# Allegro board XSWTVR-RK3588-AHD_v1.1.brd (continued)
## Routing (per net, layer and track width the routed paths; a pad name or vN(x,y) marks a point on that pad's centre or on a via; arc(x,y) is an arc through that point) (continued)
VCC1V2: length 191.8
  TOP w0.508: FB17.1 v2(141.55,19.26) v2(141.55,18.54) ; v2(59.98,23.92) v2(59.24,23.92) FB25.1
  BOTTOM w0.508: v2(54.41,19.67) 53.63,19.67 FB23.1 53.43,19.85 FB24.1 ; v2(54.41,19.67) 54.4,19.66 v2(54.4,18.97) v2(55.14,18.97) ; v2(54.41,19.67) v2(55.14,19.67) ; v2(59.98,23.92) v2(59.24,23.92) 59.24,20.36 58.55,19.67 v2(55.14,19.67) ; v2(55.14,19.67) 55.14,19.66 v2(55.14,18.97) ; 122.35,15.49 FB15.1 118.09,17.33 116.96,18.46 FB13.1 116.09,26.82 116.09,28.06 119.39,31.37 119.39,33.01 FB12.1 ; 122.35,15.49 139.81,15.49 141.55,17.23 v2(141.55,18.54) v2(141.55,19.26) 141.56,19.27 141.56,19.49 141.05,20 FB14.1 137.88,19.99 FB16.1 ; 122.35,15.49 117.2,10.33 76.23,10.33 70.22,16.35 57.72,16.35 55.14,18.94 ; 55.14,18.94 55.14,16.58 54.26,15.7 39.39,15.7 FB21.1 37.11,17.19 32.51,21.79 FB22.1 31.92,25.81 31.33,26.41 31.33,28.08 32.06,28.81 34.35,28.81 35.16,29.63 35.16,33.09 36.64,34.57 36.64,34.67 37.32,35.34 FB26.1 ; 55.14,18.94 v2(55.14,18.97)
VCC3V3_PHY0: length 33.5
  TOP w0.254: v1(127.27,85.37) 127.22,85.41 U17.29 ; R160.1 v1(133.94,82.99) ; U17.11 v1(122.77,90.21) ; R158.1 v1(133.64,81.03) ; U17.40 v1(128.85,90.21)
  TOP w0.381: R175.1 v1(119.2,91.43) C269.1 R172.2
  L3 w0.381: v1(122.77,90.21) v1(128.85,90.21)
  BOTTOM w0.381: 129.11,85.56 129.11,88.67 128.74,89.04 C273.1 128.74,90.09 v1(128.85,90.21) ; 129.11,85.56 129.11,85.44 133.51,81.03 133.64,81.03 ; 129.11,85.56 128.7,85.96 C272.1 127.86,85.96 v1(127.27,85.37) ; 122.59,90.53 122.59,90.51 122.77,90.34 v1(122.77,90.21) 122.77,89.74 C271.1 ; 122.59,90.53 C270.1 ; 122.59,90.53 122.58,90.52 120.11,90.52 v1(119.2,91.43) ; 133.64,81.03 v1(133.64,81.03) ; 133.64,81.03 133.94,81.33 v1(133.94,82.99)
VCC3V3_PHY1: length 55.7
  TOP w0.203: U19.11 145.08,90.28 v1(144.67,90.68)
  TOP w0.254: R219.1 v1(141.36,91.49) ; U19.29 149.26,85.51 v1(149.32,85.44) ; U19.40 150.92,90.28 151.31,90.66 v1(151.31,90.66)
  TOP w0.381: R203.1 v1(156.12,84.79) ; R206.2 v1(152.98,79.84) ; R201.1 v1(155.73,81.1)
  BOTTOM w0.381: 148.11,81.24 140.69,81.24 140.14,81.79 140.14,84.31 140.53,84.7 R216.2 140.76,84.81 140.76,90.9 v1(141.36,91.49) 142.39,91.49 143.84,90.04 C294.1 144.41,90.41 v1(144.67,90.68) ; 148.11,81.24 149.5,79.84 v1(152.98,79.84) 154.83,79.84 155.73,80.74 v1(155.73,81.1) 155.73,84.39 v1(156.12,84.79) ; 148.11,81.24 149.97,83.1 149.97,85.44 ; 151.31,90.42 151.31,88.4 151.58,88.12 151.58,86.94 151.2,86.56 C298.1 C296.1 149.97,85.44 ; 151.31,90.42 150.93,90.04 C299.1 ; 151.31,90.42 v1(151.31,90.66) 150.97,91 C295.1 ; 149.97,85.44 149.32,85.44 v1(149.32,85.44)
VCC3V3_SD: length 27.8
  TOP w0.305: U22.7 24.59,29.59 23.86,30.32 23.86,32.03
  TOP w0.381: 10.24,32.62 10.31,32.69
  TOP w0.508: 23.86,32.03 22.44,33.45 C323.1 10.31,32.69 ; 10.24,32.62 C324.1 10.06,26.58 11.55,25.09 J22.4
VCC3V3_SYS: length 504.7
  TOP w0.254: D21.1 v1(23.61,90.79) ; v1(23.64,92.36) R112.1 21.45,92.36 Q7.1 ; 25.75,30.33 25.47,30.33 25.25,30.1 U22.6 ; 25.75,30.33 25.75,30.64 25.61,30.77 C321.1 25.6,31.31 C322.1 24.81,30.31 v1(24.76,30.27) ; 25.75,30.33 U22.5 ; U28.9 34.7,77.2 v1(34.71,77.21) 34.73,77.21 35.2,76.74 C365.1 35.28,76.76 ; v1(59.5,146.02) 60.21,146.02 R323.2 R324.2 ; R114.1 R115.1 v1(26.43,94.84) ; R36.1 111.95,28.93 v1(111.75,28.72) ; R117.1 v1(23.6,89.47) ; R302.2 v1(60.26,130.88)
  TOP w0.305: FB18.1 33.44,31.41 32.67,30.64 v1(30.08,30.64)
  TOP w0.381: R172.1 v1(116.46,89.86) v1(115.96,89.86)
  TOP w0.508: v2(57.76,32.87) v2(57.1,32.87) ; FB9.1 112.95,36.82 112.95,36.82 v2(112.09,36.82) 112.09,37.51 112.08,37.52 112.08,38.29 D19.1 ; v1(90.88,19.96) 90.86,19.98 90.86,20.7 v1(90.87,20.71) 89.97,20.71 C349.1 89.85,20.71 88.77,20.71 C350.2 88.69,20.72 U25.16 ; v2(34.44,32.22) 34.32,32.34 34.26,32.34 34.26,32.34 FB18.1 ; v2(64.97,34.84) C375.2 65.75,34.84 U29.5 ; v2(96.33,130.29) 96.31,130.28 C257.2 ; v2(142.22,30.88) v2(141.55,30.88) ; R130.1 v2(72.71,124.69) ; U26.5 C371.2 v2(89,37.38) ; C347.1 v1(78.89,18.39)
  TOP w0.559: F2.1 96.3,128.96 C257.2
  TOP w0.762: v1(110.79,18.31) v1(111.33,18.85)
  L3 w0.254: v1(30.08,30.64) 25.13,30.64 v1(24.76,30.27)
  L3 w0.762: v2(34.44,32.22) 37.13,34.91 50.98,34.91 53.54,32.35 56.58,32.35 v2(57.1,32.87) v2(57.76,32.87) 63,32.87 v2(64.97,34.84) 66.29,34.84 68.89,32.24 v2(74.76,32.24) 74.76,32.24 74.76,33.42 ; 74.76,33.42 79.74,33.42 ; 74.76,33.42 74.76,36.14 v2(74.82,36.2) ; v2(151.54,127.28) 151.54,118.8 146.02,113.28 140.55,113.28 138.3,111.03 138.3,83.87 ; 85.42,33.42 85.35,33.49 85.35,33.5 v1(85.35,35.61) 85.35,35.64 87.1,37.38 v2(89,37.38) 91.37,35.02 99.12,35.02 100.93,36.82 v2(112.09,36.82) 112.09,36.01 111.75,35.67 v1(111.75,28.72) ; 85.42,33.42 86.37,32.48 v1(87.49,32.48) ; 85.42,33.42 79.74,33.42 ; v2(79.73,30.08) 79.73,33.41 79.74,33.42
  L3 w1.016: 138.3,83.87 139.18,82.98 140.31,82.98 v2(141.02,82.27) ; v2(141.02,82.27) v2(141.87,82.27) 141.87,82.49 143.37,83.99 152.74,83.99 ; v2(141.02,82.27) 141.02,80.74 v2(139.79,79.5) ; 68.41,32.71 v2(68.41,30.71)
  POW04 w0.305: v1(34.71,77.21) 33.36,77.21 31.94,78.63 18.06,78.63 14.7,75.28
  POW04 w0.508: 63.81,127.89 63.76,127.89 63.15,127.28 ; 63.81,127.89 63.9,127.89 64.51,127.28 ; 63.81,127.89 63.81,144.62 62.42,146.02 v1(59.5,146.02) ; 63.81,127.89 63.81,127.3 63.83,127.28 ; v1(115.96,89.86) v1(116.46,89.86) 116.9,89.86 120.34,86.42 130.44,86.42 132.34,84.51 132.85,84.51 132.86,84.51 138.78,84.51 v2(141.02,82.27) ; v2(96.33,130.29) 91.7,134.92 91.7,152.31 92.08,152.69 D43.3
  POW04 w0.762: 97.15,127.28 97.15,129.47 v2(96.33,130.29) ; 97.15,127.28 97.25,127.18 150.63,127.18 150.72,127.28 v2(151.54,127.28) ; 97.15,127.28 73.41,127.28 ; v1(60.26,130.88) 60.26,128.92 61.89,127.28 72.01,127.28 ; 73.41,127.28 72.67,127.28 ; 73.41,127.28 72.71,126.58 ; 72.67,127.28 72.01,127.28 ; 72.67,127.28 72.71,127.24 72.71,126.58 ; 72.01,127.28 72.71,126.58 72.71,126.58 ; 72.71,126.58 v2(72.71,124.69)
  BOTTOM w0.381: R274.1 85.77,36.03 v1(85.35,35.61)
  BOTTOM w0.508: R291.1 v2(81.89,25.55) R287.2 ; v1(26.43,94.84) 26.12,94.84 v1(23.64,92.36) 23.61,92.33 ; v2(79.73,30.08) 79.8,30.16 R289.2 79.81,30.85 R293.1 ; R275.1 v2(74.82,36.2) R271.2 ; R286.2 68.89,25.37 v2(68.9,25.38) R290.1 ; 23.61,92.33 v1(23.61,90.79) 23.6,90.78 v1(23.6,89.47) ; 23.61,92.33 21.95,92.33 15.57,98.7 9.34,98.7 7.57,100.47 v2(7.57,103.53) ; v2(142.22,30.88) 141.85,31.25 FB11.1 ; R288.2 v2(68.41,30.71) R292.1 ; R274.1 R270.2 ; R276.1 R272.2 86.76,31.74 v1(87.49,32.48) ; v2(141.02,82.27) v2(141.87,82.27) R211.1 140.87,83.69 R216.1 ; R277.1 74.68,32.24 v2(74.76,32.24) 75.48,31.52 R273.2
  BOTTOM w0.762: v2(57.1,32.87) 57.26,33.03 57.26,36.99 56.06,38.19 49.48,38.19 48.71,38.95 48.71,41.7 49.52,42.51 54.39,42.51 55.16,43.28 C107.1
  vias: v2(2.92,65.94) v2(2.91,65.24) v2(2.91,64.49) v2(2.9,63.79) v2(3.59,65.94) v2(3.58,65.24) v2(3.58,64.49) v2(3.57,63.79) v2(4.1,104.23) v2(4.09,103.53) v2(4.28,65.94) v2(4.27,65.24) v2(4.27,64.49) v2(4.26,63.79) v2(4.77,104.23) v2(4.76,103.53) v2(4.94,63.78) v2(4.97,65.93) v2(4.95,65.23) v2(4.96,64.48) v2(5.46,104.23) v2(5.45,103.53) v2(5.64,63.78) v2(5.67,65.93) v2(5.65,65.23) v2(5.66,64.48) v2(6.12,103.52) v2(6.15,104.22) v2(6.82,103.52) v2(6.85,104.22) v2(7.56,104.21) v2(54.66,21.69) v2(54.66,21.02) v2(65.98,15.4) v2(65.98,14.51) v2(65.97,13.7) v2(66.92,15.39) v2(66.92,14.5) v2(66.91,13.69) v2(139.11,21.83) v2(139.11,21.16) v2(142.89,37.73) v2(143.8,37.75) v2(144.67,37.77) v2(152.86,66.26) v2(152.87,65.36) v2(153.74,66.28) v2(153.75,65.38)
VCC3V9_5G: length 158.1
  L3 w0.762: v2(117.65,69.48) 118.68,70.51 128.48,70.51 136.82,78.84 136.82,111.51 139.82,114.52 145.59,114.52 150.49,119.41 v2(150.49,128.66)
  POW04 w0.508: v2(150.49,128.66) 145.93,133.22 96.4,133.22 93.22,136.4 D43.1
  BOTTOM w0.254: 12.85,41.65 12.43,41.23 R63.1 11.14,41.23 C106.1
  vias: v2(10,46.99) v2(10,46.32) v2(10.01,45.61) v2(10.72,46.99) v2(10.72,46.32) v2(10.73,45.61) v2(11.42,46.99) v2(11.42,46.32) v2(11.43,45.61) v2(12.14,46.99) v2(12.14,46.32) v2(12.15,45.61) v2(113.99,62.46) v2(113.99,61.74) v2(113.99,61.04) v2(113.99,60.32) v2(114.71,63.19) v2(114.71,62.47) v2(114.71,61.75) v2(114.71,61.05) v2(114.71,60.33) v2(115.37,62.47) v2(115.37,61.75) v2(115.37,61.05)
VCC5V0_SYS: length 84
  TOP w0.254: v1(20.43,87.42) D20.1 20.42,88.16 Q9.1
  TOP w0.305: U20.5 37.79,60.77 37.82,60.74 C308.1
  TOP w0.508: v2(78.24,27.47) C367.1 79.06,27.48 U10.10 ; U29.10 C374.1 75.41,34.84 75.97,35.4 v2(75.97,35.4) ; v2(89.31,24.92) C369.1 88.46,24.94 U10.3 ; v2(66.31,36.65) 65.74,37.22 C373.1 U29.3 ; v1(15.69,96.36) v1(15.69,96.96) D22.1 ; v2(88.98,34.72) 88.86,34.84 C370.1 U26.3 ; U26.10 79.19,37.38 C372.1 79.18,37.36 v2(79.18,36.37) ; C75.1 75.48,24.81 ; 75.48,24.81 74.83,25.46 74.83,25.5 v2(74.83,25.5) ; 75.48,24.81 U9.3 ; v2(97.71,17.14) v2(97.71,16.39) 97.71,14.92 98.48,14.15 R30.1 100.81,14.15 C56.2 101.36,14.57 U6.1 ; v2(65.24,28.18) C366.1 66.07,27.35 U9.10
  BOTTOM w0.762: v2(37.35,59.68) v2(36.6,59.68) 35.87,59.68 v2(35.85,59.69) 31.33,59.69 27.61,63.41 27.61,80.16 20.43,87.34 v1(20.43,87.42) 16.98,90.87 16.98,95.07 v1(15.69,96.36) v1(15.69,96.96)
  vias: v2(99.25,29.37) v2(123.23,47.07) v2(123.23,46.34) v2(123.23,45.65) v2(123.94,47.08) v2(123.94,46.35) v2(123.94,45.66) v2(124.61,47.08) v2(124.61,46.35) v2(124.61,45.66)
VCC5V0_USB30_HOST0: length 27.5
  TOP w0.254: R232.2 34.71,64.14 35.28,64.71 R236.1
  TOP w0.762: 25.22,63.3 C312.1
  TOP w1.016: R232.2 34.71,61.07 U20.1 31.57,60.77 30.19,62.15 C310.1 27.11,63.3 27.11,63.3 C311.1 ; C311.1 26.03,60.89 23.71,58.57 J20.1 ; C311.1 25.22,63.3
VCC5V_HDMI_TX0: length 15.8
  TOP w0.305: J17.18 7.78,90.75
  TOP w0.508: C244.1 12.91,98.24 D22.2 7.07,96.96 6.21,96.1 6.21,91.99 7.45,90.75 7.78,90.75
VCC_1V8: length 159.4
  TOP w0.254: v1(25.91,97.12) 26.69,97.12 R119.2 ; R120.2 v1(22.75,96.71)
  TOP w0.381: v1(67.98,125.15) 68.55,125.15 71.64,128.25 R133.1
  TOP w0.508: v2(54.86,120.66) 54.86,119.73 v2(54.84,119.71) FB27.1 ; R347.1 8.94,102.53
  TOP w0.635: v2(52.56,127.88) v2(52.56,126.92) ED41.1
  POW04 w0.508: v1(67.98,125.15) 66.83,124 54.86,124 54.85,124.01
  POW04 w0.762: v1(117.67,84.45) v1(117.67,84.94)
  POW04 w1.016: v1(117.67,84.94) 114.75,84.94 108.59,91.1 108.59,104.95 105.81,107.73 34.23,107.73 33.65,108.31 18.37,108.31 18.05,107.98
  BOTTOM w0.381: R167.1 v1(117.67,84.45) v1(117.67,84.94)
  BOTTOM w0.508: v2(12.97,100.63) 12.97,100.49 13.68,99.78 17.22,99.78 20.28,96.71 v1(22.75,96.71) 22.75,96.76 23.11,97.12 v1(25.91,97.12)
  vias: v2(10.92,102.76) v2(10.91,102.06) v2(10.91,101.37) v2(10.91,100.62) v2(11.63,102.75) v2(11.62,102.05) v2(11.62,101.36) v2(11.6,100.61) v2(12.34,102.03) v2(12.29,100.62) v2(12.35,102.72) v2(12.35,101.33) v2(12.98,102.74) v2(12.97,102.04) v2(12.98,101.35)
VCC_DCIN: length 3.4
  TOP w0.508: R13.2 38.62,110.71 ; R22.2 148.39,61.39
  vias: v2(8.46,14.88) v2(8.46,13.88) v2(8.46,12.88) v2(9.46,14.88) v2(9.46,13.88) v2(9.46,12.88) v2(10.46,14.88) v2(10.46,13.88) v2(10.46,12.88) v2(20.4,7.67) v2(20.4,6.67) v2(20.4,5.67) v2(21.4,7.67) v2(21.4,6.67) v2(21.4,5.67) v2(22.4,7.67) v2(22.4,6.67) v2(22.4,5.67) v2(34.33,116.34) v2(34.34,115.45) v2(34.34,114.49) v2(35.34,115.45) v2(35.34,114.49) v2(35.35,116.34) v2(36.3,116.34) v2(36.3,115.45) v2(36.31,114.54) v2(37.3,116.34) v2(37.32,115.45) v2(37.34,114.55) v2(38.27,116.35) v2(38.29,115.45) v2(38.27,114.54) v2(39.63,7.67) v2(39.63,6.67) v2(39.63,5.67) v2(40.63,7.67) v2(40.63,6.67) v2(40.63,5.67) v2(41.63,7.67) v2(41.63,6.67) v2(41.63,5.67) v2(58.88,7.59) v2(58.88,6.59) v2(58.88,5.59) v2(59.88,7.59) v2(59.88,6.59) v2(59.88,5.59) v2(60.88,7.59) v2(60.88,6.59) v2(60.88,5.59) v2(78.11,7.6) v2(78.11,6.6) v2(78.11,5.6) v2(79.11,7.6) v2(79.11,6.6) v2(79.11,5.6) v2(80.11,7.6) v2(80.11,6.6) v2(80.11,5.6) v2(97.36,7.58) v2(97.36,6.58) v2(97.36,5.58) v2(98.36,7.58) v2(98.36,6.58) v2(98.36,5.58) v2(99.36,7.58) v2(99.36,6.58) v2(99.36,5.58) v2(116.63,7.59) v2(116.63,6.59) v2(116.63,5.59) v2(117.63,7.59) v2(117.63,6.59) v2(117.63,5.59) v2(118.63,7.59) v2(118.63,6.59) v2(118.63,5.59) v2(135.86,7.61) v2(135.86,6.61) v2(135.86,5.61) v2(136.86,7.61) v2(136.86,6.61) v2(136.86,5.61) v2(137.86,7.61) v2(137.86,6.61) v2(137.86,5.61) v2(156.25,72.37) v2(156.26,71.43) v2(156.25,70.51) v2(156.27,69.61) v2(156.43,61.57) v2(156.42,60.67) v2(156.42,59.75) v2(156.44,58.85) v2(157.2,72.36) v2(157.21,71.41) v2(157.23,70.52) v2(157.25,69.62) v2(157.39,61.56) v2(157.38,60.66) v2(157.4,59.77) v2(157.41,58.86) v2(158.14,70.53) v2(158.16,72.36) v2(158.16,71.41) v2(158.16,69.63) v2(158.34,61.56) v2(158.33,60.66) v2(158.31,59.77) v2(158.33,58.87)
VCCA1V8_CODEC: length 33
  TOP w0.203: v1(47.13,113.89) 47.27,113.89 47.7,114.32 U23.16
  TOP w0.254: R257.2 v1(55.26,111.97) ; R267.2 v1(53.84,115.89)
  TOP w0.508: v2(49.27,119.23) 49.39,119.35 49.39,121.3 49.92,121.83 C342.1 51.99,120.88 C341.1 51.99,119.8 FB27.2 ; FB28.1 46.16,111.41 v1(46.16,111.83) 46.16,112.36 v1(46.18,112.37)
  BOTTOM w0.254: C332.1 51.24,118.49 v1(53.84,115.89) 55.26,114.47 v1(55.26,111.97)
  BOTTOM w0.508: v2(49.27,119.23) 49.27,118.79 C337.1 ; v1(46.16,111.83) 46.16,112.36 v1(46.18,112.37) 46.26,112.45 46.26,113.02 v1(47.13,113.89) ; C333.1 47.75,114.16 47.71,114.2 47.43,114.2 v1(47.13,113.89) ; v1(47.13,113.89) 47.13,114.15 47.14,114.16 47.14,114.6 47.11,114.64 47.11,115.5 47.13,115.53 47.13,117.99 47.64,118.5 C336.1 C337.1 ; C337.1 C331.1 50.89,118.5 C332.1
VCCIO_PHY0: length 26.9
  TOP w0.254: R169.1 v1(124.13,82.3) ; R164.1 v1(120.97,82.3) ; R174.1 v1(122.02,82.3) ; R176.1 v1(119.24,89.38) ; R171.1 v1(123.08,82.3) ; v1(126.82,85.07) U17.28
  BOTTOM w0.381: 126.78,86.65 C267.1 125.81,83.54 124.57,82.3 v1(124.13,82.3) v1(123.08,82.3) v1(122.02,82.3) v1(120.97,82.3) 120.97,82.73 ; 126.78,86.65 C268.1 ; 126.78,86.65 126.73,86.59 126.73,85.17 v1(126.82,85.07) ; R167.2 117.88,82.74 C266.1 120.96,82.74 120.97,82.73 ; v1(119.24,89.38) 120.26,89.38 120.97,88.67 120.97,82.73
VCCIO_PHY1: length 23.3
  TOP w0.254: R208.1 v1(143.09,82.36) ; R215.1 v1(145.19,82.36) ; R218.1 v1(144.14,82.36) ; U19.28 148.86,85.22 v1(148.83,85.19) ; R213.1 v1(146.25,82.36)
  TOP w0.381: R220.1 v1(141.36,89.36)
  BOTTOM w0.381: v1(148.83,85.19) 148.83,85.22 148.81,85.23 148.81,86.34 C293.1 C291.1 C292.1 147.15,83.26 v1(146.25,82.36) v1(145.19,82.36) v1(144.14,82.36) v1(143.09,82.36) 143.09,84.04 142.43,84.69 R211.2 141.87,88.85 v1(141.36,89.36)
VCCIO_WL: length 16.6
  TOP w0.127: v1(77.8,140.51) 78.14,140.16 R129.1
  TOP w0.203: v1(72.4,132.18) 72.69,131.88 U14.34
  TOP w0.508: R133.2 C255.1 U14.34
  L3 w0.203: v1(72.4,132.18) 72.4,136.87 76.03,140.51 v1(77.8,140.51)
VDD10_PHY0: length 38.3
  TOP w0.254: U17.3 126.82,91.39 v1(126.83,91.39) ; U17.38 129.34,89.41 v1(129.34,89.41) ; v1(124.82,91.38) 124.82,91.38 U17.8 ; U17.21 124.02,85.86 123.77,85.61 v1(123.55,85.61)
  BOTTOM w0.381: 129.46,89.41 129.72,89.16 129.72,86.4 131.58,84.54 134.19,84.54 134.73,83.99 134.73,80.06 134.24,79.57 v1(129.84,79.57) 129.84,80.1 v1(129.85,80.11) 129.85,80.6 v1(129.87,80.62) ; 129.46,89.41 129.46,90.61 128.69,91.39 v1(126.83,91.39) 126.49,91.05 C280.1 C279.1 125.16,91.05 ; 129.46,89.41 v1(129.34,89.41) ; 125.16,91.05 124.84,91.05 124.46,90.67 124.46,89.3 124.08,88.92 122.65,88.92 122.16,88.43 122.16,87.02 122.54,86.64 C281.1 C277.1 124.03,86.1 v1(123.55,85.61) ; 125.16,91.05 v1(124.82,91.38)
VDD10_PHY1: length 33.9
  TOP w0.203: U19.21 146.06,85.85 145.85,85.64 145.78,85.64 v1(145.65,85.64) ; v1(146.72,91.73) 146.72,91.72 146.86,91.58 U19.8 ; v1(148.83,91.68) 148.86,91.66 U19.3
  TOP w0.254: U19.38 151.37,89.48 152.2,90.3 v1(152.2,90.46)
  BOTTOM w0.381: C305.1 C302.1 C303.1 ; C305.1 v1(148.83,91.68) ; C305.1 149.39,91.62 151.69,91.62 152.2,91.12 v1(152.2,90.46) C306.1 152.54,89.7 152.93,89.32 152.93,82.07 151.71,80.85 v1(150.59,80.85) v1(150.14,80.85) v1(149.71,80.85) v1(149.3,80.85) ; C303.1 146.72,91.31 v1(146.72,91.73) ; C303.1 146.55,91.07 146.17,90.69 146.17,89.86 144.54,88.23 144.54,86.94 144.92,86.56 C307.1 C301.1 146.19,86.18 v1(145.65,85.64)
VINN1: length 0.9
  TOP w0.203: R73.1 93.04,9.84 C120.1
VINN2: length 0.9
  TOP w0.203: C121.1 117.34,9.74 R76.1
VINN3: length 0.8
  TOP w0.203: C123.1 134.03,11.44 R81.1
VINN4: length 0.8
  TOP w0.203: R82.1 144.03,10.65 C112.1
VINN5: length 0.9
  TOP w0.203: C176.1 18.39,10.62 R90.1
VINN6: length 0.9
  TOP w0.203: R93.1 37.54,9.54 C178.1
VINN7: length 1.3
  TOP w0.203: C179.1 50.49,11.55 50.85,11.19 R99.1
VINN8: length 0.8
  TOP w0.203: R97.1 69.94,11.38 C187.1
VINP1: length 1.9
  TOP w0.203: C119.1 92.17,11.43 R78.2 92.16,10.44 R71.2
VINP1_COAX: length 6.2
  TOP w0.203: R71.1 91.27,10.31 D11.1 91.27,9.34 91.27,9.33 J9.5
VINP2: length 1.9
  TOP w0.203: R74.2 R77.2 116.49,11.29 C111.1
VINP2_COAX: length 10
  TOP w0.203: R74.1 115.55,10.24 D12.1 112.43,9.26 110.51,7.34 J10.5
VINP3: length 1.9
  TOP w0.203: C122.1 133.19,12.2 R79.2 133.19,11.34 R72.2
VINP3_COAX: length 7.8
  TOP w0.203: J11.5 129.76,7.92 131.1,9.27 D14.1 132.19,9.35 R72.1
VINP4: length 1.9
  TOP w0.203: R75.2 144.9,9.84 R80.2 144.85,9.81 C124.1
VINP4_COAX: length 9.1
  TOP w0.203: R75.1 145.91,10.85 D13.1 147.94,10.85 149,9.79 J12.5
VINP5: length 2.2
  TOP w0.203: C175.1 16.59,11.86 R94.2 R88.2
VINP5_COAX: length 6.8
  TOP w0.203: R88.1 15.7,10.31 D15.1 14.3,7.95 J13.5
VINP6: length 2.2
  TOP w0.203: 35.66,10.33 R95.2 36.16,10.88 C177.1
  TOP w0.254: R91.2 R95.2
VINP6_COAX: length 6.3
  TOP w0.203: J14.5 33.54,9.44 D16.1
  TOP w0.254: R91.1 34.48,9.46 D16.1
VINP7: length 2.2
  TOP w0.203: 49.87,10.36 R98.2 ; R98.2 50.11,10.55 50.11,11.17 C186.1 ; R98.2 49.93,10.34 R89.2
VINP7_COAX: length 6.6
  TOP w0.203: J15.5 52.78,8.63 D17.1 51.03,9.45 R89.1
VINP8: length 2.4
  TOP w0.203: C180.1 69.1,9.65 69.6,10.15 69.6,10.16 69.94,10.51 R96.2 ; 69.89,10.61 R96.2 ; R96.2 69.94,10.61 R92.2
VINP8_COAX: length 6.5
  TOP w0.203: R92.1 71.03,9.69 D18.1 72.03,9.66 J16.5
5G_3V3: length 30.5
  TOP w0.254: v1(46.57,45.74) v1(46.57,44.72) 46.57,44.72 v1(46.57,43.7)
  L3 w0.508: v1(29.68,36.17) 29.68,37.98 31.41,39.71 40.18,39.71 44.17,43.7 v1(46.57,43.7)
  BOTTOM w0.254: Q3.3 48.45,46.18 47.13,46.18 46.69,45.74 v1(46.57,45.74) R54.2 ; R345.1 v1(29.68,36.17) ; R53.2 v1(46.57,44.72) ; R52.2 v1(46.57,43.7)
5G_3V9: length 20
  BOTTOM w0.508: v2(18.59,40.76) 18.59,41.45 18.15,41.89 C83.2 C82.2 18.15,46.22 C80.2 18.13,47.04 C81.2 18.15,48.06 C79.1 19.23,48.71 20.45,47.48 22.61,47.48 J2.2 ; 41.37,46.9 42.21,47.74 C87.1 C91.1 C92.1 C88.1 ; v2(17.21,40.75) 16.29,40.75 Q2.3
  vias: v2(17.21,40.03) v2(17.88,40.75) v2(17.88,40.03) v2(18.59,40.04) v2(49.39,50.05) v2(49.39,49.39) v2(49.4,48.67) v2(50.11,50.05) v2(50.11,49.39) v2(50.12,48.67) v2(50.81,50.05) v2(50.81,49.39) v2(50.82,48.67) v2(51.54,50.05) v2(51.54,49.39) v2(51.55,48.67)
5G_PWR_OFF: length 113.2
  TOP w0.127: v1(106.88,33.81) 106.88,35.91 106.89,35.91 J24.3
  L3 w0.127: v1(23.6,45.77) 23.6,44.81 19.32,40.54 19.32,32.12 22.64,28.8 50.35,28.8 51.88,27.28 60.6,27.28 60.99,26.89 72.8,26.89 73.34,26.35 84.61,26.35 87.89,29.63 96.96,29.63 99.77,32.43 105.51,32.43 v1(106.88,33.81)
  BOTTOM w0.127: v1(23.6,45.77) 23.8,45.98 J2.6
5G_PWRER_CTR: length 95.7
  TOP w0.127: J24.8 v1(104.39,33.84)
  L3 w0.127: v1(19.72,36.31) 20.14,35.9 20.14,31.78 22.86,29.06 50.48,29.06 51.74,27.8 56.68,27.8 56.91,28.03 57.21,28.03 57.57,27.67 72.45,27.67 73.52,26.6 84.51,26.6 87.78,29.88 87.82,29.88 87.92,29.98 96.87,29.98 99.65,32.75 103.3,32.75 v1(104.39,33.84)
  BOTTOM w0.127: R67.1 v1(19.72,36.31)
5G_RESET: length 84.4
  TOP w0.127: J24.12 v1(102.39,33.52)
  L3 w0.127: v1(23.75,29.78) 36.2,29.78 36.67,29.31 50.71,29.31 51.55,28.47 53.26,28.47 53.94,29.15 72.35,29.15 73.61,27.89 85.34,27.89 87.71,30.26 96.71,30.26 99.71,33.26 102.13,33.26 v1(102.39,33.52)
  BOTTOM w0.127: R55.1 23.75,30.15 23.75,30.15 v1(23.75,29.78)
5G_USB_DM: length 43
  TOP w0.127: U28.5 v1(31.8,76.8)
  L3 w0.127: v1(31.8,76.8) 31.5,77.06 28.81,77.06 24.51,72.76 24.51,42.39 v1(24.67,42.23)
  BOTTOM w0.127: v1(24.67,42.23) 24.44,42.01 24.44,40.53 24.55,40.42 J2.9
5G_USB_DP: length 43.5
  TOP w0.127: U28.3 v1(31.75,77.6)
  L3 w0.127: v1(31.75,77.6) 31.53,77.34 28.69,77.34 24.23,72.88 24.23,42.53 v1(23.94,42.23)
  BOTTOM w0.127: J2.7 24.05,40.39 24.16,40.5 24.16,42.01 v1(23.94,42.23)
5G_VBUS: length 23.1
  TOP w0.305: v1(32.38,79.81) 35.94,79.81 36.38,79.36 R330.1 ; v1(32.4,74.62) 29.97,72.2 J21.1
  BOTTOM w0.305: v1(32.4,74.62) 32.4,75.08 32.38,75.1 v1(32.38,79.81)
5G_W_DISABLE1#: length 24.5
  BOTTOM w0.127: J2.8 24.3,44.72 25.76,43.27 25.76,38.93 24.97,38.14 23.07,38.14 22.47,37.54 22.47,29.95 23.13,29.28 25.62,29.28 25.74,29.4 R51.1
5G_WAKE_MCU: length 78.5
  TOP w0.127: v1(96.02,30.98) 96.02,30.4 97.17,29.25 97.17,27.85 97.48,27.53 U8.33
  L3 w0.127: v1(96.02,30.98) 87.44,30.98 84.86,28.4 74.05,28.4 72.78,29.66 66.82,29.66 66.67,29.82 37.33,29.82 36.54,30.61 32.09,30.61 29.97,32.72 29.94,32.72 v1(29.68,32.98)
  BOTTOM w0.127: v1(29.68,32.98) R345.2 28.83,33.47 Q32.3
5G_WAKE_ON_WAN: length 3.9
  BOTTOM w0.127: J2.23 28.05,38.8 28.37,38.48 Q32.2
5G_WAKEUP_IN: length 118.1
  TOP w0.127: U1.214 88.31,106.87 v1(88.77,106.42)
  L3 w0.127: v1(31.8,49.09) 32.06,49.35 36.74,49.35 39.31,51.92 39.31,53.67 42.21,56.58 42.21,100.22 49.33,107.34 87.89,107.34 88.27,107.71 90.72,107.71 91.7,106.73 91.7,106.38 91.41,106.09 90.12,106.09 89.79,106.42 v1(88.77,106.42)
  BOTTOM w0.127: J2.38 v1(31.8,49.09)
5G_WWAN_LED#: length 158.5
  TOP w0.203: v1(88.98,149.46) 88.24,149.46 86.77,147.99 R348.1
  L3 w0.127: v1(88.98,149.46) 88.98,146.94 85.92,143.88 85.92,112.71 81.55,108.34 67.58,108.34 66.12,109.81 61.44,109.81 60.38,108.75 56.92,108.75 55.21,110.46 50.37,110.46 40.23,100.31 40.23,57.47 34.16,51.41 32.3,51.41 30.62,49.73 25.52,49.73 v1(25.12,49.34)
  BOTTOM w0.127: J2.10 24.8,49.02 v1(25.12,49.34)
27M_CLK_XI: length 5.6
  TOP w0.203: R83.2 120.31,36.58 ; 120.31,36.58 R85.1 ; 120.31,36.58 120.21,36.67 C132.1 119.05,36.41 117.21,36.41 Y1.3
27M_CLK_XI1: length 5.6
  TOP w0.203: R105.1 35.86,36.44 ; 35.86,36.44 35.76,36.53 C197.1 34.61,36.27 32.77,36.27 Y2.3 ; 35.86,36.44 R101.2
ACC: length 25.9
  TOP w0.381: R304.2 54.92,139.84 51.53,143.23 42.27,143.23 U24.C4
ACC_CHECK: length 159.7
  TOP w0.102: 59.11,129.33 59.54,129.76 59.77,129.76 60.21,129.32 R302.1
  TOP w0.127: ED45.2 60.27,129.34 R302.1 ; R39.2 104.18,31.4 103.58,32 99.69,32 97.89,33.81 J24.21 97.89,37.91 99.5,39.53 v1(99.87,39.53) ; Q30.3 59.11,129.33 59.11,127.65 58.54,127.08 58.54,111.65 56.07,109.18 v1(54.63,109.18)
  BOTTOM w0.127: v1(54.63,109.18) 52.06,106.61 51.67,106.61 51.67,106.61 49.99,106.61 49.18,105.8 49.18,61.22 49.48,60.92 56.69,60.92 58.46,59.15 71.48,59.15 73.15,57.48 73.15,42.57 73.62,42.1 76.35,42.1 76.6,41.85 97.55,41.85 v1(99.87,39.53)
AHD_I2C_SCL: length 163.4
  TOP w0.127: v1(130.67,38.03) 130.85,37.86 138.13,37.86 139.62,36.37 139.62,28.38 138.8,27.56 U11.49 ; v1(61.94,24.58) 61.88,24.64 61.88,26.58 60.31,28.15 55.98,28.15 R107.2 55.26,27.42 U13.49 ; v1(83.13,40.27) 82.18,41.23 80.97,41.23 80.31,41.89 U1.99
  L3 w0.127: v1(130.67,38.03) 129.91,38.79 124.7,38.79 123.8,39.69 112.52,39.69 111.46,38.63 93.42,38.63 91.87,40.18 83.22,40.18 v1(83.13,40.27)
  BOTTOM w0.127: v1(83.13,40.27) 83.71,40.85 97.1,40.85 99.97,37.98 99.97,35.9 98.58,34.52 95.77,34.52 91.71,30.45 91.71,18.02 90.62,16.93 88.3,16.93 84.8,20.44 65.56,20.44 61.94,24.06 v1(61.94,24.58)
AHD_I2C_SDA: length 163.1
  TOP w0.127: v1(130.33,37.53) 138.01,37.53 139.22,36.32 139.22,28.55 138.63,27.96 U11.50 ; v1(82.76,39.9) 81.79,40.87 80.3,40.87 79.31,41.86 U1.98 ; U13.50 54.67,27.82 R106.1 55.98,29.14 59.93,29.14 62.33,26.74 v1(62.33,25.23)
  L3 w0.127: v1(130.33,37.53) 129.54,38.32 124.5,38.32 123.52,39.31 112.77,39.31 111.79,38.33 93.32,38.33 91.75,39.9 v1(82.76,39.9)
  BOTTOM w0.127: v1(82.76,39.9) 83.35,39.9 83.95,40.51 96.97,40.51 99.6,37.88 99.6,35.96 98.49,34.85 95.62,34.85 91.26,30.49 91.26,18.09 90.43,17.26 88.54,17.26 85.04,20.76 65.73,20.76 62.33,24.15 v1(62.33,25.23)
AHD_RSTN: length 179.3
  TOP w0.127: U13.47 54.64,26.62 55.17,27.16 60.68,27.16 61.57,26.27 v1(61.57,24.09) ; v1(130.82,38.7) 131.34,38.19 138.42,38.19 140.09,36.52 140.09,28.23 138.63,26.76 U11.47 ; U1.95 76.31,41.59 77.5,40.4 v1(77.5,40.33)
  L3 w0.127: v1(130.82,38.7) 131.07,38.46 131.07,37.46 130.7,37.1 130.09,37.1 129.31,37.87 124.33,37.87 123.31,38.89 113.02,38.89 112.16,38.04 93.18,38.04 91.62,39.6 85.74,39.6 85,38.85 77.91,38.85 77.5,39.26 v1(77.5,40.33)
  BOTTOM w0.127: v1(77.5,40.33) 77.5,40.93 77.75,41.19 97.21,41.19 100.31,38.09 100.31,35.77 98.76,34.21 96.11,34.21 92,30.1 92,17.82 90.75,16.58 88.12,16.58 84.57,20.13 65.37,20.13 61.57,23.92 v1(61.57,24.09)
ARM_BOOT: length 11.4
  TOP w0.127: R303.2 26.14,123.95 ED46.1 25.19,124.97 24.2,125.97 24.2,131.9 U24.K2
ARM_CAN0_H: length 143.2
  TOP w0.127: R335.1 76.57,34.13 76.57,35.42 77.77,36.63 77.77,36.63 78.23,37.09 78.23,40.25 78.46,40.47 78.8,40.47 v1(79.15,40.12) ; U24.G3 31.89,135.71 38.18,135.71 38.97,134.92 38.97,125.83 38.2,125.06 ED33.1 v1(38.77,123.96)
  BOTTOM w0.127: v1(79.15,40.12) 79.15,40.05 78.76,39.65 75.82,39.65 75.27,40.2 66.14,40.2 65,41.34 65,49.79 55.22,59.56 48.72,59.56 47.67,60.61 47.67,93.56 47.67,93.56 47.67,93.57 44.42,96.82 44.42,119.54 40.38,123.59 39.14,123.59 v1(38.77,123.96)
ARM_CAN0_L: length 136.3
  TOP w0.127: v1(78.62,40.09) 78.49,39.96 78.49,36.99 78.03,36.53 78.03,36.53 77.03,35.53 R337.1 ; U24.F3 34.02,136.08 38.23,136.08 39.22,135.09 39.22,124.59 39.41,124.4 ED36.1 v1(39.98,123.96)
  BOTTOM w0.127: v1(39.98,123.96) 40.68,123.96 44.75,119.88 44.75,96.92 47.98,93.69 47.98,60.74 48.88,59.84 55.49,59.84 65.38,49.95 65.38,41.53 66.37,40.54 75.44,40.54 76.02,39.97 78.49,39.97 v1(78.62,40.09)
ARM_CAN1_H: length 133.6
  TOP w0.127: v1(49.98,123.97) 49.98,123.97 ED43.1 49.43,124.69 46.82,127.29 46.82,137.28 U24.B4 ; R338.1 77.24,39.41 76.34,40.31 v1(76.34,40.33)
  BOTTOM w0.127: v1(49.98,123.97) 49.6,123.59 45.71,123.59 44.36,122.23 44.36,120.85 45.09,120.12 45.09,97.04 48.31,93.82 48.31,60.9 49.1,60.11 55.79,60.11 65.78,50.12 65.78,41.78 66.61,40.95 75.7,40.95 76.32,40.33 v1(76.34,40.33)
ARM_CAN1_L: length 135.1
  TOP w0.127: U24.A4 45.32,139.35 47.15,137.52 47.15,127.52 ED42.1 51.25,123.97 v1(51.25,123.97) ; v1(76.88,40.34) 77.7,39.52 77.7,37.9 R340.1
  BOTTOM w0.127: v1(51.25,123.97) 50.61,123.33 46.24,123.33 45.04,122.13 45.04,120.73 45.41,120.37 45.41,97.15 48.63,93.92 48.63,61.04 49.29,60.39 56.12,60.39 66.15,50.35 66.15,42.02 66.85,41.32 75.9,41.32 76.24,40.98 76.73,40.98 76.88,40.84 v1(76.88,40.34)
ARM_CAN2_EN: length 7.5
  TOP w0.127: U26.6 85.67,38.65 82.81,41.51 81.69,41.51 81.31,41.88 U1.100
ARM_CAN2_NSTB: length 14.4
  TOP w0.127: U1.97 78.31,41.9 79.65,40.57 81.55,40.57 82.25,39.87 82.25,32.82 81.73,32.3 U26.14
ARM_CAN3_EN: length 34.5
  TOP w0.127: v1(90.92,31.66) 70.44,31.66 68.53,33.57 U29.6 ; J24.20 98.39,35.42 98.32,35.48 v1(98.32,35.89)
  BOTTOM w0.127: v1(90.92,31.66) 94.77,35.51 97.95,35.51 v1(98.32,35.89)
ARM_CAN3_NSTB: length 2.9
  TOP w0.127: U29.14 73.31,40.03 U1.92
BOOT: length 221.4
  TOP w0.127: D44.2 v1(113.55,14.14)
  BOTTOM w0.127: U24.B3 41.64,136.1 41.64,126.25 40.46,125.06 18.66,125.06 17.99,124.39 17.99,122.64 34.75,105.88 34.75,85.91 35.12,85.53 35.12,62.73 41.76,56.09 41.76,55.15 42.87,54.04 46.95,54.04 46.97,54.02 51.38,54.02 58.53,46.87 58.53,37.17 58.56,37.14 58.56,29.08 60.59,27.05 60.59,23.39 64.79,19.19 83.1,19.19 91.47,10.82 112.54,10.82 113.55,11.83 v1(113.55,14.14)
BOOT0: length 12.3
  TOP w0.127: U8.60 106.17,19.07 106.35,19.25 109.55,19.25 110.09,18.71 Q31.3 110.18,12.89 R343.1
BOOT_SARADC_IN0: length 164.8
  TOP w0.127: R303.1 26.27,122.17 v1(26.26,122.16) ; 107.38,35.53 v1(107.38,35.57) 107.39,35.56 J24.2
  L3 w0.127: v1(107.38,35.57) 106.96,35.16 100.34,35.16 96.49,31.31 96.21,31.31 96.17,31.35 95.87,31.35 95.83,31.31 87.26,31.31 84.6,28.66 74.17,28.66 72.9,29.92 66.93,29.92 v1(64.99,31.86)
  BOTTOM w0.127: v1(64.99,31.86) 61.47,35.37 61.47,48.02 52.94,56.55 45.12,56.55 39.14,62.52 39.14,118.74 38.3,119.58 31.67,119.58 29.09,122.16 v1(26.26,122.16)
BT&WIFI_ANT: length 10.4
  TOP w0.559: R132.1 76.93,149.78 C254.1 78.15,151 78.15,156.19 arc(78.43,156.87) 79.11,157.16 J18.2
BT_RST: length 30.4
  TOP w0.127: v1(69.96,109.15) 69.31,108.51 U1.233 ; U14.38 v1(77.75,133.32)
  L3 w0.127: v1(77.75,133.32) 76.55,132.12 76.55,115.75 v1(69.96,109.15)
BT_WAKE_HOST_H: length 42.4
  TOP w0.127: U14.50 76.79,144.12 78.96,141.96 78.96,114.49 80.26,113.19 83.25,113.19 86.31,110.13 U1.216
CAN1_RX: length 41.2
  TOP w0.127: U8.61 106.67,17.01 105.87,16.21 100.17,16.21 98.22,18.17 92.68,18.17 91.68,19.16 91.68,21.06 91.04,21.7 77.33,21.7 76.02,23.01 76.02,25.51 75.45,26.08 U9.4
CAN1_RX_M1: length 16.3
  TOP w0.127: J24.19 98.49,36.93 v1(98.38,36.82) ; v1(88.98,36.4) 86.8,36.4 U26.4
  BOTTOM w0.127: v1(88.98,36.4) 90.31,36.4 93.8,39.89 97.11,39.89 98.38,38.62 v1(98.38,36.82)
CAN1_TX: length 38.8
  TOP w0.127: U9.1 76.31,22.27 77.15,21.44 90.95,21.44 91.42,20.97 91.42,19.07 92.57,17.91 98.11,17.91 100.06,15.96 105.98,15.96 107.17,17.16 U8.62
CAN1_TX_M1: length 16.2
  TOP w0.127: J24.18 99.39,35.77 99.27,35.89 v1(98.9,35.89) ; U26.1 86.7,32.12 87.33,32.12 87.41,32.03 91.27,32.03 v1(91.66,31.64)
  BOTTOM w0.127: v1(98.9,35.89) 98.21,35.2 95.22,35.2 91.92,31.91 91.92,31.9 v1(91.66,31.64)
CAN2_RX: length 25.3
  TOP w0.127: U10.4 89.1,26.21 89.95,25.36 89.95,23.58 92.19,21.34 92.19,19.42 92.76,18.86 98.39,18.86 100.47,16.78 104.42,16.78 104.67,17.04 U8.57
CAN2_RX_M0: length 16.5
  TOP w0.127: U29.4 68.36,36.77 77.41,36.77 77.98,37.34 77.98,40.82 77.31,41.48 U1.96
CAN2_TX: length 23.4
  TOP w0.127: U8.58 105.17,17.14 104.56,16.52 100.37,16.52 98.29,18.6 92.66,18.6 91.94,19.31 91.94,21.23 90.78,22.4 U10.1
CAN2_TX_M0: length 10.2
  TOP w0.127: U1.93 74.31,39.53 74.1,39.32 68.54,39.32 67.94,39.92 U29.1
CAN_WAKEUP_0: length 26.9
  TOP w0.102: 75.78,29.62 R351.1
  TOP w0.127: U8.37 97.48,25.53 95.8,27.21 95.8,28.43 94.15,30.08 91.09,30.08 90.31,30.86 76.16,30.86 75.78,30.48 R352.2 75.78,29.62
CAN_WAKEUP_1: length 13.3
  TOP w0.127: R354.2 89.29,29.21 R353.1 90.26,30.06 90.96,29.37 93.88,29.37 95.16,28.08 95.16,26.85 97.48,24.53 U8.39
CAN_WAKEUP_2: length 19.2
  TOP w0.127: U8.34 97.48,27.03 96.8,27.71 96.8,29.07 94.78,31.09 92.91,31.09 89.79,34.2 89.79,39.01 89.24,39.57 R356.2 89.25,39.63 R355.1
CAN_WAKEUP_3: length 36.3
  TOP w0.102: R357.1 66.04,30.48 R358.2
  TOP w0.127: U8.35 97.46,26.53 96.47,27.52 96.47,28.87 94.59,30.76 91.3,30.76 90.68,31.38 66.92,31.38 66.84,31.29 R357.1
CORE_INPUT1: length 12.3
  TOP w0.127: v1(93.88,39.42) 93.88,37.98 93.89,37.98 J24.29
  BOTTOM w0.127: v1(93.88,39.42) 93.88,39.05 90.86,36.03 R270.1 87.77,36.05 Q14.3
CORE_INPUT2: length 27.5
  TOP w0.127: v1(94.38,39.42) 94.38,35.58 94.39,35.58 J24.28
  BOTTOM w0.127: v1(94.38,39.42) 94.38,39.05 90.54,35.21 78.4,35.21 77.42,36.2 R271.1 76.45,36.2 76.18,36.47 76.17,36.47 75.96,36.68 75.96,38.27 Q15.3
CORE_INPUT3: length 14.5
  TOP w0.127: J24.27 94.89,37.98 94.88,37.98 v1(94.88,39.42)
  BOTTOM w0.127: v1(94.88,39.42) 94.88,39.05 89.55,33.72 Q16.3 88,33.47 88,31.89 R272.1
CORE_INPUT4: length 30.9
  TOP w0.127: v1(95.38,39.42) 95.38,35.58 95.39,35.58 J24.26
  BOTTOM w0.127: v1(95.38,39.42) 95.38,39.05 88.91,32.59 88.91,31.51 88.09,30.69 84.02,30.69 83.26,31.45 R273.1 75.98,31.95 75.98,33.44 Q17.3
CORE_OUTPUT1: length 32.9
  TOP w0.127: J24.25 v1(95.89,35.99)
  BOTTOM w0.127: R297.1 75.71,22.22 D37.1 76.53,21.7 87.97,21.7 90.51,24.23 90.51,31.87 94.64,35.99 v1(95.89,35.99)
CORE_OUTPUT2: length 23.3
  TOP w0.127: v1(96.39,37.59) 96.39,37.06 96.39,37.06 J24.24
  BOTTOM w0.127: R294.1 87.85,22.39 D38.1 88.02,22.55 90.16,24.69 90.16,32.17 95.59,37.59 v1(96.39,37.59)
CORE_OUTPUT3: length 34.1
  TOP w0.127: v1(96.88,38.99) 96.88,37.98 96.89,37.98 J24.23
  BOTTOM w0.127: D39.1 75.75,27.43 ; 75.75,27.43 75.75,26.45 76.15,26.05 88.85,26.05 89.78,26.98 89.78,32.38 96.39,38.99 v1(96.88,38.99) ; 75.75,27.43 75.72,27.4 R295.1
CORE_OUTPUT4: length 22.7
  TOP w0.127: v1(96.87,39.49) 97.24,39.49 97.39,39.34 J24.22
  BOTTOM w0.127: v1(96.87,39.49) 96.32,39.49 89.36,32.54 89.36,28.88 87.99,27.51 D40.1 87.94,27.49 87.81,27.36 R296.1
DEBUG_DM: length 2.5
  TOP w0.127: R240.2 31.13,76.54 31.25,76.42 32.89,76.42 33.01,76.55 U28.6
DEBUG_DM0: length 17.8
  TOP w0.127: R240.1 29.13,77.1 28.81,77.1 28.37,77.1 28.12,76.85 28.12,76.79 ED19.1 27.33,77.09 25.32,77.09 25.07,77.08 24.88,76.9 24.56,76.9 24.38,77.08 24.05,77.08 23.87,76.9 23.54,76.9 23.36,77.08 23.04,77.08 22.85,76.9 22.53,76.9 22.34,77.08 19.07,77.08 17.12,75.13 17.12,73.06 J21.2
DEBUG_DP: length 2.4
  TOP w0.127: U28.2 33.01,77.84 32.89,77.97 31.17,77.97 31.14,77.94 R242.2
DEBUG_DP0: length 17.9
  TOP w0.127: J21.3 16.84,73.06 16.84,75.25 18.95,77.36 25.21,77.36 27.29,77.36 ED20.1 27.86,77.92 28.41,77.38 28.81,77.38 29.13,77.38 R242.1
ETH0_REFCLKO_25M: length 76.2
  TOP w0.127: R148.1 130.91,90.88 131.22,91.19 132.57,91.19 v1(132.87,91.5) ; U1.227 v1(75.31,109.67)
  BOTTOM w0.127: v1(132.87,91.5) 132.87,95.53 132.05,96.35 116.05,96.35 113.76,98.64 113.76,105.12 108.74,110.14 76.32,110.14 75.84,109.67 v1(75.31,109.67)
ETH1_REFCLKO_25M: length 68.6
  TOP w0.127: R193.1 152.94,90.94 153.25,91.24 154.47,91.24 v1(154.88,91.65) ; U1.156 v1(113.91,70.84)
  BOTTOM w0.127: v1(113.91,70.84) 127.8,70.84 131.34,74.38 151.29,74.38 158.51,81.6 158.51,90.86 157.72,91.65 v1(154.88,91.65)
GMAC0_MCLKINOUT: length 83.8
  TOP w0.127: U1.223 79.31,108.81 80.23,109.73 v1(80.23,110.64) ; R155.1 130.97,85.13 C264.1 R156.1 v1(133.74,85.13)
  BOTTOM w0.127: v1(80.23,110.64) 80.24,110.65 108.82,110.65 114.13,105.33 114.13,98.78 116.16,96.76 132.77,96.76 136.71,92.82 136.71,86.17 135.68,85.13 v1(133.74,85.13)
GMAC0_MDC: length 98.8
  TOP w0.127: v1(115.26,88.85) 115.62,89.22 116.28,89.22 116.42,89.08 116.46,89.08 116.46,89.08 118.42,89.08 119.24,89.9 121.18,89.9 121.68,89.41 U17.13 ; U1.250 v1(52.31,109.17)
  L3 w0.127: v1(52.31,109.17) 53.81,107.67 82.17,107.67 87.71,113.21 111.11,113.21 116.25,108.06 116.25,101.56 115.31,100.62 115.31,88.91 v1(115.26,88.85)
GMAC0_MDIO: length 84.9
  TOP w0.127: v1(115.83,88.85) 115.84,88.85 115.97,88.71 120.2,88.71 R176.2 121.24,89.01 U17.14 ; v1(66.05,109.19) 66.31,108.93 U1.236
  L3 w0.127: v1(66.05,109.19) 67.25,107.99 81.92,107.99 87.43,113.5 111.18,113.5 116.51,108.17 116.51,101.45 115.57,100.5 115.57,89.11 v1(115.83,88.85) 115.83,88.86 115.78,88.9
GMAC0_RSTN_L: length 101.3
  TOP w0.127: U1.94 v1(75.31,45.93) ; v1(111.6,82.45) 113.14,83.99 113.14,87.6 115.02,89.48 116.47,89.48 116.62,89.33 118.23,89.33 119.31,90.42 R177.1
  BOTTOM w0.127: v1(75.31,45.93) 75.31,43.67 76.81,42.17 97.77,42.17 101.14,38.8 108.42,38.8 110.99,41.37 110.99,60.95 110.66,61.28 110.66,73.84 113.68,76.86 113.68,79.26 111.6,81.34 v1(111.6,82.45)
GMAC0_RXCLK: length 98
  TOP w0.127: U1.162 111.55,76.84 112.01,76.37 112.68,76.37 112.81,76.25 112.81,76.01 112.94,75.89 113.19,75.89 113.32,76.01 113.32,76.25 113.45,76.37 113.7,76.37 113.83,76.25 113.83,76.01 113.95,75.89 114.21,75.89 114.33,76.01 114.33,76.25 114.46,76.37 114.72,76.37 114.84,76.25 114.84,76.01 114.97,75.89 115.22,75.89 115.35,76.01 115.35,76.25 115.48,76.37 115.73,76.37 115.86,76.25 115.86,76.01 115.99,75.89 116.24,75.89 116.37,76.01 116.37,76.25 116.49,76.37 116.75,76.37 116.87,76.25 116.87,76.01 117,75.89 117.26,75.89 117.38,76.01 117.38,76.25 117.65,76.52 123.8,76.52 124.64,77.35 124.71,77.35 v1(124.97,77.61) ; v1(125.52,77.99) 125.52,78.37 126.12,78.96 C282.1 126.24,78.97 R182.2
  L3 w0.127: v1(125.52,77.99) 126.25,77.99 126.51,77.73 126.51,76.29 126.84,75.95 128.4,75.95 128.87,75.49 128.87,71.84 128.27,71.24 121.16,71.24 121.03,71.37 121.03,71.69 121.16,71.81 127.95,71.81 128.08,71.94 128.08,72.2 127.95,72.32 121.16,72.32 121.03,72.45 121.03,72.7 121.16,72.83 127.95,72.83 128.08,72.96 128.08,73.21 127.95,73.34 121.16,73.34 121.03,73.47 121.03,73.72 121.16,73.85 127.95,73.85 128.08,73.97 128.08,74.23 127.95,74.35 121.16,74.35 121.03,74.48 121.03,74.74 121.16,74.86 127.95,74.86 128.08,74.99 128.08,75.24 127.95,75.37 125.09,75.37 124.97,75.5 124.97,75.85 125.09,75.97 125.95,75.97 126.08,76.1 126.08,76.35 125.95,76.48 125.09,76.48 124.97,76.61 v1(124.97,77.61)
GMAC0_RXD0: length 99.3
  TOP w0.127: v1(60.69,110.37) 60.69,110.37 58.31,110.37 57.31,109.37 U1.245 ; v1(111.51,77.31) 112.46,77.31 112.59,77.18 122.96,77.18 124.08,78.3 R178.2
  BOTTOM w0.127: v1(111.51,77.31) 109.75,79.07 109.75,105.3 107.2,107.86 61.57,107.86 60.69,108.73 v1(60.69,110.37)
GMAC0_RXD1: length 94
  TOP w0.127: U1.237 v1(65.31,109.18) ; R179.2 123.08,77.86 122.74,77.53 112.9,77.53 112.68,77.75 v1(111.87,77.75)
  BOTTOM w0.127: v1(111.87,77.75) 111.43,77.75 110.06,79.12 110.06,105.62 107.58,108.11 74.12,108.11 73.99,108.24 73.99,108.54 73.86,108.66 73.61,108.66 73.48,108.54 73.48,108.24 73.35,108.11 73.1,108.11 72.97,108.24 72.97,108.54 72.85,108.66 72.59,108.66 72.47,108.54 72.47,108.24 72.34,108.11 72.08,108.11 71.96,108.24 71.96,108.54 71.83,108.66 71.58,108.66 71.45,108.54 71.45,108.24 71.32,108.11 71.07,108.11 70.94,108.24 70.94,108.54 70.81,108.66 70.56,108.66 70.43,108.54 70.43,108.24 70.31,108.11 70.05,108.11 69.93,108.24 69.93,108.54 69.8,108.66 69.54,108.66 69.42,108.54 69.42,108.24 69.29,108.11 69.04,108.11 68.91,108.24 68.91,108.54 68.78,108.66 68.53,108.66 68.4,108.54 68.4,108.24 68.27,108.11 68.02,108.11 67.89,108.24 67.89,108.54 67.77,108.66 67.51,108.66 67.39,108.54 67.39,108.24 67.26,108.11 66.38,108.11 v1(65.31,109.18)
GMAC0_RXD2: length 90.7
  TOP w0.127: v1(112.34,78.6) 113.04,77.9 v1(117.06,77.9) ; R180.2 122.41,77.92 v1(122.5,77.92) ; v1(111.67,79.84) 111.44,79.84 U1.165
  L3 w0.127: v1(122.5,77.92) 124.23,77.92 124.35,77.79 124.35,77.43 124.23,77.31 119.43,77.31 119.3,77.18 119.3,76.93 119.43,76.8 124.23,76.8 124.35,76.67 124.35,75.68 124.13,75.46 123.86,75.46 123.73,75.58 123.73,76.19 123.61,76.32 123.35,76.32 123.23,76.19 123.23,75.58 123.1,75.46 122.85,75.46 122.72,75.58 122.72,76.19 122.59,76.32 122.34,76.32 122.21,76.19 122.21,75.58 122.08,75.46 121.83,75.46 121.7,75.58 121.7,76.19 121.58,76.32 121.32,76.32 121.19,76.19 121.19,75.58 121.07,75.46 120.83,75.46 120.42,75.04 120.42,74.75 120.29,74.62 117.72,74.62 117.59,74.49 117.59,74.24 117.72,74.11 120.29,74.11 120.42,73.98 120.42,73.73 120.29,73.6 117.72,73.6 117.59,73.48 117.59,73.22 117.72,73.1 120.29,73.1 120.42,72.97 120.42,72.71 120.29,72.59 117.72,72.59 117.59,72.46 117.59,72.21 117.72,72.08 120.29,72.08 120.42,71.95 120.42,71.45 120.29,71.33 117.21,71.33 117.04,71.5 117.04,75.21 117.16,75.34 118.24,75.34 118.36,75.46 118.36,75.72 118.24,75.84 117.16,75.84 117.04,75.97 117.04,76.93 118.15,78.04 118.15,78.3 118.02,78.43 117.56,78.43 117.44,78.55 117.44,78.81 117.56,78.93 118.02,78.93 118.15,79.06 118.15,79.31 118.02,79.44 117.56,79.44 117.44,79.57 117.44,79.82 117.56,79.95 118.02,79.95 118.15,80.08 118.15,80.38 118.02,80.51 116.36,80.51 116.23,80.64 116.23,80.89 116.36,81.02 118.02,81.02 118.15,81.15 118.15,81.4 118.02,81.53 116.36,81.53 116.23,81.65 116.23,81.91 116.36,82.04 118.02,82.04 118.15,82.16 118.15,82.42 118.02,82.54 116.36,82.54 116.23,82.67 116.23,82.92 116.36,83.05 118.02,83.05 118.15,83.18 118.15,83.62 118.02,83.75 115.77,83.75 115.58,83.56 115.58,80.35 117.06,78.87 v1(117.06,77.9) ; v1(112.34,78.6) 111.67,79.27 v1(111.67,79.84)
GMAC0_RXD3: length 90
  TOP w0.127: U1.164 110.97,78.84 111.23,79.1 112.52,79.1 113.32,78.3 118.38,78.3 v1(118.76,77.93) ; R181.2 120.33,78.94 v1(120.33,79.16)
  L3 w0.127: v1(118.76,77.93) 118.69,77.99 118.69,78.76 118.82,78.89 119.66,78.89 119.79,79.01 119.79,79.27 119.66,79.39 118.82,79.39 118.69,79.52 118.69,79.78 118.82,79.9 119.66,79.9 119.79,80.03 119.79,80.28 119.66,80.41 118.82,80.41 118.69,80.54 118.69,80.79 118.82,80.92 119.66,80.92 119.79,81.05 119.79,81.3 119.66,81.43 118.82,81.43 118.69,81.55 118.69,81.81 118.82,81.93 119.66,81.93 119.79,82.06 119.79,82.32 119.66,82.44 118.82,82.44 118.69,82.57 118.69,82.82 118.82,82.95 119.66,82.95 119.79,83.08 119.79,83.33 119.66,83.46 118.82,83.46 118.69,83.59 118.69,84.14 119.64,85.08 119.64,86.51 119.77,86.63 120.12,86.63 120.25,86.51 120.25,85.19 120.38,85.07 120.63,85.07 120.76,85.19 120.76,86.51 120.88,86.63 121.14,86.63 121.26,86.51 121.26,85.19 121.39,85.07 121.65,85.07 121.77,85.19 121.77,86.51 121.9,86.63 122.15,86.63 122.28,86.51 122.28,85.19 122.41,85.07 122.66,85.07 122.79,85.19 122.79,86.51 122.92,86.63 124.22,86.63 124.35,86.51 124.35,85.36 124.47,85.23 124.73,85.23 124.85,85.36 124.85,86.51 124.98,86.63 125.23,86.63 125.36,86.51 125.36,85.36 125.49,85.23 125.74,85.23 125.87,85.36 125.87,86.51 126,86.63 127.83,86.63 127.96,86.51 127.96,85.34 128.09,85.21 128.34,85.21 128.47,85.34 128.47,86.51 128.62,86.66 129.01,86.66 129.14,86.53 129.14,83.26 128.99,83.12 128.48,83.12 128.36,83.24 128.36,84.35 128.23,84.48 127.98,84.48 127.85,84.35 127.85,83.24 127.72,83.12 127.47,83.12 127.34,83.24 127.34,84.35 127.21,84.48 126.96,84.48 126.83,84.35 126.83,83.24 126.71,83.12 126.45,83.12 126.32,83.24 126.32,84.37 126.2,84.5 125.94,84.5 125.82,84.37 125.82,83.24 125.69,83.12 125.44,83.12 125.31,83.24 125.31,84.37 125.18,84.5 124.93,84.5 124.8,84.37 124.8,83.24 124.67,83.12 124.42,83.12 124.29,83.24 124.29,84.37 124.17,84.5 123.91,84.5 123.78,84.37 123.78,83.24 123.66,83.12 123.4,83.12 123.28,83.24 123.28,84.37 123.15,84.5 122.9,84.5 122.77,84.37 122.77,83.24 122.64,83.12 122.39,83.12 122.26,83.24 122.26,84.37 122.13,84.5 121.88,84.5 121.75,84.37 121.75,83.24 121.63,83.12 120.57,83.12 120.33,82.88 120.33,81.93 120.46,81.8 121.6,81.8 121.72,81.67 121.72,81.42 121.6,81.29 120.46,81.29 120.33,81.16 v1(120.33,79.16)
GMAC0_RXDV_CRS: length 100.2
  TOP w0.127: R183.2 125.19,78.47 123.58,76.87 v1(112.18,76.87) ; v1(74.31,109.17) 74.31,109.17 U1.228
  BOTTOM w0.127: v1(74.31,109.17) 74.36,109.12 74.43,109.12 75.16,108.39 80.24,108.39 80.36,108.52 80.36,108.71 80.49,108.84 80.74,108.84 80.87,108.71 80.87,108.52 81,108.39 81.25,108.39 81.38,108.52 81.38,108.71 81.51,108.84 81.76,108.84 81.89,108.71 81.89,108.52 82.01,108.39 82.27,108.39 82.4,108.52 82.4,108.71 82.52,108.84 82.78,108.84 82.9,108.71 82.9,108.52 83.03,108.39 83.28,108.39 83.41,108.52 83.41,108.71 83.54,108.84 83.79,108.84 83.92,108.71 83.92,108.52 84.05,108.39 84.3,108.39 84.43,108.52 84.43,108.71 84.55,108.84 84.81,108.84 84.94,108.71 84.94,108.52 85.06,108.39 85.32,108.39 85.44,108.52 85.44,108.71 85.57,108.84 85.82,108.84 85.95,108.71 85.95,108.52 86.08,108.39 86.33,108.39 86.46,108.52 86.46,108.71 86.59,108.84 86.84,108.84 86.97,108.71 86.97,108.52 87.09,108.39 87.35,108.39 87.48,108.52 87.48,108.71 87.6,108.84 87.86,108.84 87.98,108.71 87.98,108.52 88.11,108.39 88.36,108.39 88.49,108.52 88.49,108.71 88.62,108.84 88.87,108.84 89,108.71 89,108.52 89.13,108.39 89.38,108.39 89.51,108.52 89.51,108.71 89.63,108.84 89.89,108.84 90.02,108.71 90.02,108.52 90.14,108.39 90.4,108.39 90.52,108.52 90.52,108.71 90.65,108.84 90.9,108.84 91.03,108.71 91.03,108.52 91.16,108.39 91.41,108.39 91.54,108.52 91.54,108.71 91.67,108.84 91.92,108.84 92.05,108.71 92.05,108.52 92.17,108.39 92.43,108.39 92.56,108.52 92.56,108.71 92.68,108.84 92.94,108.84 93.06,108.71 93.06,108.52 93.19,108.39 93.44,108.39 93.57,108.52 93.57,108.71 93.7,108.84 93.95,108.84 94.08,108.71 94.08,108.52 94.21,108.39 94.46,108.39 94.59,108.52 94.59,108.71 94.71,108.84 94.97,108.84 95.1,108.71 95.1,108.52 95.22,108.39 95.48,108.39 95.6,108.52 95.6,108.71 95.73,108.84 95.98,108.84 96.11,108.71 96.11,108.52 96.24,108.39 96.49,108.39 96.62,108.52 96.62,108.71 96.75,108.84 97,108.84 97.13,108.71 97.13,108.52 97.25,108.39 97.51,108.39 97.64,108.52 97.64,108.71 97.76,108.84 98.02,108.84 98.14,108.71 98.14,108.52 98.27,108.39 98.52,108.39 98.65,108.52 98.65,108.71 98.78,108.84 99.03,108.84 99.16,108.71 99.16,108.52 99.29,108.39 99.54,108.39 99.67,108.52 99.67,108.71 99.79,108.84 100.05,108.84 100.18,108.71 100.18,108.52 100.3,108.39 100.56,108.39 100.68,108.52 100.68,108.71 100.81,108.84 101.06,108.84 101.19,108.71 101.19,108.52 101.32,108.39 101.57,108.39 101.7,108.52 101.7,108.71 101.83,108.84 102.08,108.84 102.21,108.71 102.21,108.52 102.33,108.39 102.59,108.39 102.72,108.52 102.72,108.71 102.84,108.84 103.1,108.84 103.22,108.71 103.22,108.52 103.35,108.39 103.6,108.39 103.73,108.52 103.73,108.71 103.86,108.84 104.11,108.84 104.24,108.71 104.24,108.52 104.37,108.39 104.62,108.39 104.75,108.52 104.75,108.71 104.87,108.84 105.13,108.84 105.26,108.71 105.26,108.52 105.38,108.39 105.64,108.39 105.76,108.52 105.76,108.71 105.89,108.84 106.14,108.84 106.27,108.71 106.27,108.52 106.4,108.39 106.65,108.39 106.78,108.52 106.78,108.71 106.91,108.84 107.16,108.84 107.29,108.71 107.29,108.52 107.41,108.39 107.67,108.39 110.43,105.63 110.43,79.97 112.38,78.02 112.38,77.08 v1(112.18,76.87)
GMAC0_TXCLK: length 62.6
  TOP w0.127: U1.163 111.29,77.84 v1(111.61,78.16) ; v1(114.12,78.67) 114.53,78.67 114.65,78.8 114.65,82.61 114.78,82.74 117.89,82.74 118.02,82.61 118.02,82.36 117.89,82.23 115.29,82.23 115.16,82.1 115.16,81.85 115.29,81.72 117.89,81.72 118.02,81.59 118.02,81.34 117.89,81.21 115.29,81.21 115.16,81.09 115.16,80.83 115.29,80.7 117.89,80.7 118.02,80.58 118.02,80.32 117.89,80.2 115.29,80.2 115.16,80.07 115.16,79.82 115.29,79.69 117.89,79.69 118.02,79.56 118.02,79.31 117.89,79.18 115.29,79.18 115.16,79.05 115.16,78.8 115.29,78.67 119.27,78.67 119.86,79.26 119.86,79.82 119.74,79.95 118.59,79.95 118.46,80.07 118.46,80.33 118.59,80.45 119.74,80.45 119.86,80.58 119.86,80.84 119.74,80.96 118.59,80.96 118.46,81.09 118.46,81.34 118.59,81.47 119.74,81.47 119.86,81.6 119.86,81.85 119.74,81.98 118.59,81.98 118.46,82.11 118.46,82.36 118.59,82.49 119.74,82.49 119.86,82.61 119.86,82.87 119.74,82.99 118.59,82.99 118.46,83.12 118.46,83.38 118.59,83.5 119.74,83.5 119.86,83.63 119.86,83.88 119.74,84.01 118.59,84.01 118.46,84.14 118.46,84.39 118.59,84.52 119.74,84.52 119.86,84.65 119.86,85.58 C274.1 120.88,86.6 U17.20
  L3 w0.127: v1(111.61,78.16) 113.6,78.16 v1(114.12,78.67)
GMAC0_TXD0: length 69.9
  TOP w0.127: U1.229 v1(73.31,109.61) ; v1(116.37,87.44) 123.39,87.44 U17.18
  BOTTOM w0.127: v1(116.37,87.44) 115.53,87.44 111.05,91.92 111.05,106.49 108.08,109.46 78.01,109.46 77.6,109.05 75.03,109.05 74.46,109.61 v1(73.31,109.61)
GMAC0_TXD1: length 65.5
  TOP w0.127: U1.225 77.31,109.4 v1(77.36,109.44) ; U17.17 v1(115.99,87.81)
  BOTTOM w0.127: v1(115.99,87.81) 115.69,87.81 111.39,92.1 111.39,106.85 108.45,109.78 77.69,109.78 v1(77.36,109.44)
GMAC0_TXD2: length 64.5
  TOP w0.127: U17.16 121.6,88.2 121.56,88.17 v1(121.56,88.17) ; U1.166 111.13,80.84 116.08,85.78 v1(116.83,85.78)
  L3 w0.127: v1(116.83,85.78) 116.85,85.78 117.48,86.42 117.48,86.81 117.61,86.94 118.62,86.94 118.75,87.07 118.75,87.32 118.62,87.45 117.61,87.45 117.48,87.57 117.48,87.83 117.61,87.95 118.62,87.95 118.75,88.08 118.75,88.34 118.62,88.46 117.61,88.46 117.48,88.59 117.48,88.84 117.61,88.97 118.62,88.97 118.75,89.1 118.75,89.35 118.62,89.48 117.61,89.48 117.48,89.61 117.48,90.82 117.61,90.95 118.68,90.95 118.81,91.07 118.81,91.33 118.68,91.46 117.77,91.46 117.64,91.58 117.64,91.84 117.77,91.96 118.68,91.96 118.81,92.09 118.81,92.34 118.68,92.48 117.78,92.48 117.66,92.6 117.66,93.22 117.95,93.51 117.95,93.93 118.07,94.06 119.01,94.06 119.14,94.19 119.14,94.44 119.01,94.57 118.07,94.57 117.9,94.74 117.9,95.01 119.01,96.11 119.44,96.11 119.57,95.99 119.57,94.77 119.73,94.61 119.95,94.61 120.07,94.73 120.07,95.99 120.2,96.11 120.45,96.11 120.58,95.99 120.58,94.73 120.71,94.61 120.96,94.61 121.09,94.73 121.09,95.99 121.22,96.11 122.94,96.11 123.08,95.97 123.08,95.6 122.96,95.47 122.47,95.47 122.34,95.35 122.34,95.09 122.47,94.97 122.96,94.97 123.08,94.84 123.08,94.59 122.96,94.46 122.47,94.46 122.34,94.33 122.34,94.08 122.47,93.95 122.96,93.95 123.08,93.82 123.08,91.98 121.94,90.84 121.76,90.84 120.91,91.69 120.73,91.69 120.55,91.51 120.55,91.33 121.4,90.48 121.4,90.3 121.22,90.12 121.05,90.12 120.19,90.97 120.01,90.97 119.83,90.79 119.83,90.61 120.55,89.89 120.55,89.71 119.36,88.52 119.36,87.58 119.49,87.45 121.34,87.45 121.56,87.67 v1(121.56,88.17)
GMAC0_TXD3: length 62.5
  TOP w0.127: v1(115.53,85.77) 111.59,81.84 U1.167 ; v1(120.17,88.21) 120.6,88.63 123.4,88.63 U17.15
  L3 w0.127: v1(120.17,88.21) 123.47,91.5 124.27,91.5 125.42,92.65 125.42,94.51 125.29,94.63 123.74,94.63 123.61,94.76 123.61,95.01 123.74,95.14 125.29,95.14 125.42,95.27 125.42,95.52 125.29,95.65 123.74,95.65 123.61,95.78 123.61,96.03 123.74,96.16 125.29,96.16 125.42,96.28 125.42,97.1 125.09,97.43 124.3,97.43 124.17,97.3 124.17,96.78 124.05,96.65 123.79,96.65 123.66,96.78 123.66,97.3 123.54,97.43 123.28,97.43 123.16,97.3 123.16,96.78 123.03,96.65 122.78,96.65 122.65,96.78 122.65,97.3 122.52,97.43 122.27,97.43 122.14,97.3 122.14,96.78 122.01,96.65 121.76,96.65 121.63,96.78 121.63,97.3 121.51,97.43 121.25,97.43 121.12,97.3 121.12,96.78 121,96.65 120.74,96.65 120.62,96.78 120.62,97.3 120.49,97.43 120.24,97.43 120.11,97.3 120.11,96.78 119.98,96.65 119.73,96.65 119.6,96.78 119.6,97.3 119.47,97.43 119.22,97.43 119.09,97.3 119.09,96.78 118.97,96.65 118.71,96.65 118.58,96.78 118.58,97.3 118.46,97.43 118.2,97.43 118.08,97.3 118.08,96.78 117.95,96.65 117.7,96.65 117.57,96.78 117.57,97.3 117.44,97.43 116.77,97.43 116.55,97.2 116.55,96.57 116.67,96.44 117.2,96.44 117.33,96.32 117.33,96.06 117.2,95.94 116.67,95.94 116.55,95.81 116.55,95.56 116.67,95.43 117.2,95.43 117.33,95.3 117.33,95.05 117.2,94.92 116.67,94.92 116.55,94.79 116.55,92.77 116.67,92.64 116.95,92.64 117.08,92.52 117.08,92.26 116.95,92.13 116.67,92.13 116.55,92.01 116.55,91.75 116.67,91.63 116.95,91.63 117.08,91.5 117.08,91.25 116.95,91.12 116.67,91.12 116.55,90.99 116.55,90.66 116.88,90.33 116.88,87.06 115.59,85.77 v1(115.53,85.77)
GMAC0_TXEN: length 64
  TOP w0.127: U17.19 123.37,87.06 v1(115.87,87.06) ; U1.224 v1(78.31,109.09)
  BOTTOM w0.127: v1(115.87,87.06) 115.31,87.06 110.71,91.66 110.71,106.23 107.85,109.09 v1(78.31,109.09)
GMAC1_MCLKINOUT: length 72.9
  TOP w0.127: v1(156.8,85.22) 155.16,85.22 R199.1 155.05,85.2 C289.1 153,85.2 R198.1 ; U1.141 v1(111.65,55.84)
  BOTTOM w0.127: v1(156.8,85.22) 156.8,80.78 150.79,74.76 131.09,74.76 127.6,71.28 113.79,71.28 113.24,70.73 113.24,63.07 112.41,62.23 112.41,56.59 v1(111.65,55.84)
